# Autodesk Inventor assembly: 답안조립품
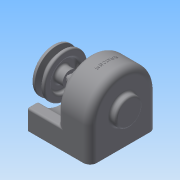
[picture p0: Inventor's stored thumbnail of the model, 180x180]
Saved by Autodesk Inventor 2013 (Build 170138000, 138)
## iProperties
Created: 2015-02
Part Number: 답안조립품
Document SubType Name: Assembly
Designer: Administrator
Author: Administrator
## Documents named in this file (14)
- C:\Documents and Settings\Administrator\바탕 화면\450214V1025\답안조립품.iam
- C:\Documents and Settings\Administrator\바탕 화면\450214V1025\1-본체.ipt
- C:\Documents and Settings\Administrator\바탕 화면\450214V1025\베어링 6001.ipt
- C:\Documents and Settings\Administrator\바탕 화면\450214V1025\키5x5.ipt
- C:\Documents and Settings\Administrator\바탕 화면\450214V1025\축.ipt
- C:\Documents and Settings\Administrator\바탕 화면\450214V1025\5-스퍼기어.ipt
- C:\Documents and Settings\Administrator\바탕 화면\450214V1025\축커버.ipt
- C:\Documents and Settings\Administrator\바탕 화면\450214V1025\오일실.ipt
- C:\Documents and Settings\Administrator\바탕 화면\450214V1025\4-V-벨트풀리.ipt
- C:\Documents and Settings\Administrator\바탕 화면\450214V1025\키4x4.ipt
- C:\Documents and Settings\Administrator\바탕 화면\450214V1025\와샤.ipt
- C:\Documents and Settings\Administrator\바탕 화면\450214V1025\M5x0.8.ipt
- M5x0.8.ipt
- C:\Documents and Settings\Administrator\바탕 화면\450214V1025\M3x0.5.ipt
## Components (7 placed, 4 different names)
1. 1-본체:1 — 각도:5
2. 4-V-벨트풀리:1 — 플러쉬:1, 각도:4
3. M5x0.8:1 — 각도:5
4. M3x0.5:1
5. M3x0.5:2
6. M3x0.5:3
7. M3x0.5:4
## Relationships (3: Angle 2, Flush 1)
- 플러쉬:1 [Flush]: 4-V-벨트풀리:1
- 각도:4 [Angle]: 4-V-벨트풀리:1
- 각도:5 [Angle]: 1-본체:1 ↔ M5x0.8:1
